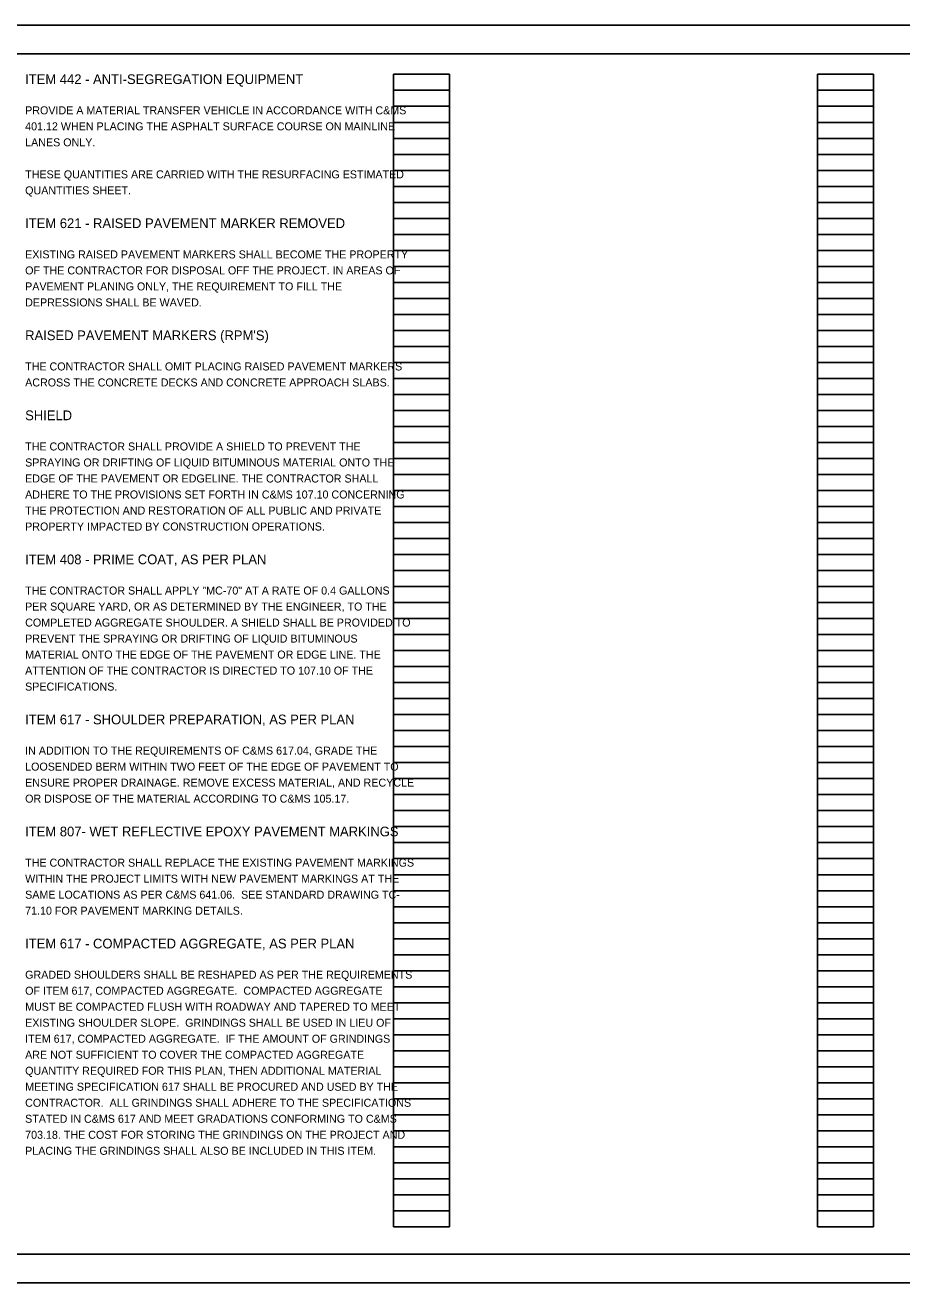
# Model space of a CAD drawing. Extents: x 0 to 49.4, y 0 to 22.1.
# Drawn here: x 9.82 to 25.15, y 0 to 22 of the extents above; entities that cross this region are included whole.
import ezdxf

# ---------------------------------------------------------------- set-up
doc = ezdxf.new("R2010")
doc.units = 0
for name, color, linetype in [('SH_Border', 7, 'Continuous'), ('SH_Cut_Line', 7, 'Continuous'), ('SH_Data', 7, 'Continuous'), ('SH_Text', 7, 'Continuous')]:
    doc.layers.add(name, color=color, linetype=linetype)

msp = doc.modelspace()

# ---------------------------------------------------------------- linework, layer by layer
at = {"layer": 'SH_Border'}
msp.add_lwpolyline([(1.5, 21.5), (33.5, 21.5), (33.5, 0.5), (1.5, 0.5)], close=True, dxfattribs=at)
at = {"layer": 'SH_Cut_Line'}
msp.add_lwpolyline([(0, 0), (34, 0), (34, 22), (0, 22)], close=True, dxfattribs=at)
at = {"layer": 'SH_Data'}
for p, q in [((16.26, 0.98), (16.26, 21.14)), ((16.26, 21.14), (17.24, 21.14)), ((17.24, 0.98), (17.24, 21.14)), ((23.68, 0.98), (23.68, 21.14)), ((23.68, 21.14), (24.66, 21.14)), ((24.66, 0.98), (24.66, 21.14)), ((16.26, 20.86), (17.24, 20.86)), ((23.68, 20.86), (24.66, 20.86)), ((16.26, 20.58), (17.24, 20.58)), ((23.68, 20.58), (24.66, 20.58)), ((16.26, 20.3), (17.24, 20.3)), ((23.68, 20.3), (24.66, 20.3)), ((16.26, 20.02), (17.24, 20.02)), ((23.68, 20.02), (24.66, 20.02)), ((16.26, 19.74), (17.24, 19.74)), ((23.68, 19.74), (24.66, 19.74)), ((16.26, 19.46), (17.24, 19.46)), ((23.68, 19.46), (24.66, 19.46)), ((16.26, 19.18), (17.24, 19.18)), ((23.68, 19.18), (24.66, 19.18)), ((16.26, 18.9), (17.24, 18.9)), ((23.68, 18.9), (24.66, 18.9)), ((16.26, 18.62), (17.24, 18.62)), ((23.68, 18.62), (24.66, 18.62)), ((16.26, 18.34), (17.24, 18.34)), ((23.68, 18.34), (24.66, 18.34)), ((16.26, 18.06), (17.24, 18.06)), ((23.68, 18.06), (24.66, 18.06)), ((16.26, 17.78), (17.24, 17.78)), ((23.68, 17.78), (24.66, 17.78)), ((16.26, 17.5), (17.24, 17.5)), ((23.68, 17.5), (24.66, 17.5)), ((16.26, 17.22), (17.24, 17.22)), ((23.68, 17.22), (24.66, 17.22)), ((16.26, 16.94), (17.24, 16.94)), ((23.68, 16.94), (24.66, 16.94)), ((16.26, 16.66), (17.24, 16.66)), ((23.68, 16.66), (24.66, 16.66)), ((16.26, 16.38), (17.24, 16.38)), ((23.68, 16.38), (24.66, 16.38)), ((16.26, 16.1), (17.24, 16.1)), ((23.68, 16.1), (24.66, 16.1)), ((16.26, 15.82), (17.24, 15.82)), ((23.68, 15.82), (24.66, 15.82)), ((16.26, 15.54), (17.24, 15.54)), ((23.68, 15.54), (24.66, 15.54)), ((16.26, 15.26), (17.24, 15.26)), ((23.68, 15.26), (24.66, 15.26)), ((16.26, 14.98), (17.24, 14.98)), ((23.68, 14.98), (24.66, 14.98)), ((16.26, 14.7), (17.24, 14.7)), ((23.68, 14.7), (24.66, 14.7)), ((16.26, 14.42), (17.24, 14.42)), ((23.68, 14.42), (24.66, 14.42)), ((16.26, 14.14), (17.24, 14.14)), ((23.68, 14.14), (24.66, 14.14)), ((16.26, 13.86), (17.24, 13.86)), ((23.68, 13.86), (24.66, 13.86)), ((16.26, 13.58), (17.24, 13.58)), ((23.68, 13.58), (24.66, 13.58)), ((16.26, 13.3), (17.24, 13.3)), ((23.68, 13.3), (24.66, 13.3)), ((16.26, 13.02), (17.24, 13.02)), ((23.68, 13.02), (24.66, 13.02)), ((16.26, 12.74), (17.24, 12.74)), ((23.68, 12.74), (24.66, 12.74)), ((16.26, 12.46), (17.24, 12.46)), ((23.68, 12.46), (24.66, 12.46)), ((16.26, 12.18), (17.24, 12.18)), ((23.68, 12.18), (24.66, 12.18)), ((16.26, 11.9), (17.24, 11.9)), ((23.68, 11.9), (24.66, 11.9)), ((16.26, 11.62), (17.24, 11.62)), ((23.68, 11.62), (24.66, 11.62)), ((16.26, 11.34), (17.24, 11.34)), ((23.68, 11.34), (24.66, 11.34)), ((16.26, 11.06), (17.24, 11.06)), ((23.68, 11.06), (24.66, 11.06)), ((16.26, 10.78), (17.24, 10.78)), ((23.68, 10.78), (24.66, 10.78)), ((16.26, 10.5), (17.24, 10.5)), ((23.68, 10.5), (24.66, 10.5)), ((16.26, 10.22), (17.24, 10.22)), ((23.68, 10.22), (24.66, 10.22)), ((16.26, 9.94), (17.24, 9.94)), ((23.68, 9.94), (24.66, 9.94)), ((16.26, 9.66), (17.24, 9.66)), ((23.68, 9.66), (24.66, 9.66)), ((16.26, 9.38), (17.24, 9.38)), ((23.68, 9.38), (24.66, 9.38)), ((16.26, 9.1), (17.24, 9.1)), ((23.68, 9.1), (24.66, 9.1)), ((16.26, 8.82), (17.24, 8.82)), ((23.68, 8.82), (24.66, 8.82)), ((16.26, 8.54), (17.24, 8.54)), ((23.68, 8.54), (24.66, 8.54)), ((16.26, 8.26), (17.24, 8.26)), ((23.68, 8.26), (24.66, 8.26)), ((16.26, 7.98), (17.24, 7.98)), ((23.68, 7.98), (24.66, 7.98)), ((16.26, 7.7), (17.24, 7.7)), ((23.68, 7.7), (24.66, 7.7)), ((16.26, 7.42), (17.24, 7.42)), ((23.68, 7.42), (24.66, 7.42)), ((16.26, 7.14), (17.24, 7.14)), ((23.68, 7.14), (24.66, 7.14)), ((16.26, 6.86), (17.24, 6.86)), ((23.68, 6.86), (24.66, 6.86)), ((16.26, 6.58), (17.24, 6.58)), ((23.68, 6.58), (24.66, 6.58)), ((16.26, 6.3), (17.24, 6.3)), ((23.68, 6.3), (24.66, 6.3)), ((16.26, 6.02), (17.24, 6.02)), ((23.68, 6.02), (24.66, 6.02)), ((16.26, 5.74), (17.24, 5.74)), ((23.68, 5.74), (24.66, 5.74)), ((16.26, 5.46), (17.24, 5.46)), ((23.68, 5.46), (24.66, 5.46)), ((16.26, 5.18), (17.24, 5.18)), ((23.68, 5.18), (24.66, 5.18)), ((16.26, 4.9), (17.24, 4.9)), ((23.68, 4.9), (24.66, 4.9)), ((16.26, 4.62), (17.24, 4.62)), ((23.68, 4.62), (24.66, 4.62)), ((16.26, 4.34), (17.24, 4.34)), ((23.68, 4.34), (24.66, 4.34)), ((16.26, 4.06), (17.24, 4.06)), ((23.68, 4.06), (24.66, 4.06)), ((16.26, 3.78), (17.24, 3.78)), ((23.68, 3.78), (24.66, 3.78)), ((16.26, 3.5), (17.24, 3.5)), ((23.68, 3.5), (24.66, 3.5)), ((16.26, 3.22), (17.24, 3.22)), ((23.68, 3.22), (24.66, 3.22)), ((16.26, 2.94), (17.24, 2.94)), ((23.68, 2.94), (24.66, 2.94)), ((16.26, 2.66), (17.24, 2.66)), ((23.68, 2.66), (24.66, 2.66)), ((16.26, 2.38), (17.24, 2.38)), ((23.68, 2.38), (24.66, 2.38)), ((16.26, 2.1), (17.24, 2.1)), ((23.68, 2.1), (24.66, 2.1)), ((16.26, 1.82), (17.24, 1.82)), ((23.68, 1.82), (24.66, 1.82)), ((16.26, 1.54), (17.24, 1.54)), ((23.68, 1.54), (24.66, 1.54)), ((16.26, 1.26), (17.24, 1.26)), ((23.68, 1.26), (24.66, 1.26)), ((16.26, 0.98), (17.24, 0.98)), ((23.68, 0.98), (24.66, 0.98))]:
    msp.add_line(p, q, dxfattribs=at)

# ---------------------------------------------------------------- texts
at = {"layer": 'SH_Text'}
for s, height, p in [('ITEM 442 - ANTI-SEGREGATION EQUIPMENT', 0.17, (9.82, 20.97)), ('PROVIDE A MATERIAL TRANSFER VEHICLE IN ACCORDANCE WITH C&MS ', 0.14, (9.82, 20.44)), ('401.12 WHEN PLACING THE ASPHALT SURFACE COURSE ON MAINLINE ', 0.14, (9.82, 20.16)), ('LANES ONLY.', 0.14, (9.82, 19.88)), ('THESE QUANTITIES ARE CARRIED WITH THE RESURFACING ESTIMATED ', 0.14, (9.82, 19.32)), ('QUANTITIES SHEET.', 0.14, (9.82, 19.04)), ('ITEM 621 - RAISED PAVEMENT MARKER REMOVED', 0.17, (9.82, 18.45)), ('EXISTING RAISED PAVEMENT MARKERS SHALL BECOME THE PROPERTY ', 0.14, (9.82, 17.92)), ('OF THE CONTRACTOR FOR DISPOSAL OFF THE PROJECT. IN AREAS OF ', 0.14, (9.82, 17.64)), ('PAVEMENT PLANING ONLY, THE REQUIREMENT TO FILL THE ', 0.14, (9.82, 17.36)), ('DEPRESSIONS SHALL BE WAVED. ', 0.14, (9.82, 17.08)), ("RAISED PAVEMENT MARKERS (RPM'S)", 0.17, (9.82, 16.49)), ('THE CONTRACTOR SHALL OMIT PLACING RAISED PAVEMENT MARKERS ', 0.14, (9.82, 15.96)), ('ACROSS THE CONCRETE DECKS AND CONCRETE APPROACH SLABS.', 0.14, (9.82, 15.68)), ('SHIELD', 0.17, (9.82, 15.09)), ('THE CONTRACTOR SHALL PROVIDE A SHIELD TO PREVENT THE ', 0.14, (9.82, 14.56)), ('SPRAYING OR DRIFTING OF LIQUID BITUMINOUS MATERIAL ONTO THE ', 0.14, (9.82, 14.28)), ('EDGE OF THE PAVEMENT OR EDGELINE. THE CONTRACTOR SHALL ', 0.14, (9.82, 14)), ('ADHERE TO THE PROVISIONS SET FORTH IN C&MS 107.10 CONCERNING ', 0.14, (9.82, 13.72)), ('THE PROTECTION AND RESTORATION OF ALL PUBLIC AND PRIVATE ', 0.14, (9.82, 13.44)), ('PROPERTY IMPACTED BY CONSTRUCTION OPERATIONS.', 0.14, (9.82, 13.16)), ('ITEM 408 - PRIME COAT, AS PER PLAN', 0.17, (9.82, 12.57)), ('THE CONTRACTOR SHALL APPLY "MC-70" AT A RATE OF 0.4 GALLONS ', 0.14, (9.82, 12.04)), ('PER SQUARE YARD, OR AS DETERMINED BY THE ENGINEER, TO THE ', 0.14, (9.82, 11.76)), ('COMPLETED AGGREGATE SHOULDER. A SHIELD SHALL BE PROVIDED TO ', 0.14, (9.82, 11.48)), ('PREVENT THE SPRAYING OR DRIFTING OF LIQUID BITUMINOUS ', 0.14, (9.82, 11.2)), ('MATERIAL ONTO THE EDGE OF THE PAVEMENT OR EDGE LINE. THE ', 0.14, (9.82, 10.92)), ('ATTENTION OF THE CONTRACTOR IS DIRECTED TO 107.10 OF THE ', 0.14, (9.82, 10.64)), ('SPECIFICATIONS. ', 0.14, (9.82, 10.36)), ('ITEM 617 - SHOULDER PREPARATION, AS PER PLAN', 0.17, (9.82, 9.77)), ('IN ADDITION TO THE REQUIREMENTS OF C&MS 617.04, GRADE THE ', 0.14, (9.82, 9.24)), ('LOOSENDED BERM WITHIN TWO FEET OF THE EDGE OF PAVEMENT TO ', 0.14, (9.82, 8.96)), ('ENSURE PROPER DRAINAGE. REMOVE EXCESS MATERIAL, AND RECYCLE ', 0.14, (9.82, 8.68)), ('OR DISPOSE OF THE MATERIAL ACCORDING TO C&MS 105.17.', 0.14, (9.82, 8.4)), ('ITEM 807- WET REFLECTIVE EPOXY PAVEMENT MARKINGS', 0.17, (9.82, 7.81)), ('THE CONTRACTOR SHALL REPLACE THE EXISTING PAVEMENT MARKINGS ', 0.14, (9.82, 7.28)), ('WITHIN THE PROJECT LIMITS WITH NEW PAVEMENT MARKINGS AT THE ', 0.14, (9.82, 7)), ('SAME LOCATIONS AS PER C&MS 641.06.  SEE STANDARD DRAWING TC-', 0.14, (9.82, 6.72)), ('71.10 FOR PAVEMENT MARKING DETAILS.', 0.14, (9.82, 6.44)), ('ITEM 617 - COMPACTED AGGREGATE, AS PER PLAN', 0.17, (9.82, 5.85)), ('GRADED SHOULDERS SHALL BE RESHAPED AS PER THE REQUIREMENTS ', 0.14, (9.82, 5.32)), ('OF ITEM 617, COMPACTED AGGREGATE.  COMPACTED AGGREGATE ', 0.14, (9.82, 5.04)), ('MUST BE COMPACTED FLUSH WITH ROADWAY AND TAPERED TO MEET ', 0.14, (9.82, 4.76)), ('EXISTING SHOULDER SLOPE.  GRINDINGS SHALL BE USED IN LIEU OF ', 0.14, (9.82, 4.48)), ('ITEM 617, COMPACTED AGGREGATE.  IF THE AMOUNT OF GRINDINGS ', 0.14, (9.82, 4.2)), ('ARE NOT SUFFICIENT TO COVER THE COMPACTED AGGREGATE ', 0.14, (9.82, 3.92)), ('QUANTITY REQUIRED FOR THIS PLAN, THEN ADDITIONAL MATERIAL ', 0.14, (9.82, 3.64)), ('MEETING SPECIFICATION 617 SHALL BE PROCURED AND USED BY THE ', 0.14, (9.82, 3.36)), ('CONTRACTOR.  ALL GRINDINGS SHALL ADHERE TO THE SPECIFICATIONS ', 0.14, (9.82, 3.08)), ('STATED IN C&MS 617 AND MEET GRADATIONS CONFORMING TO C&MS ', 0.14, (9.82, 2.8)), ('703.18. THE COST FOR STORING THE GRINDINGS ON THE PROJECT AND ', 0.14, (9.82, 2.52)), ('PLACING THE GRINDINGS SHALL ALSO BE INCLUDED IN THIS ITEM.', 0.14, (9.82, 2.24))]:
    msp.add_text(s, height=height, dxfattribs=at).set_placement(p)

doc.saveas('drawing.dxf')
